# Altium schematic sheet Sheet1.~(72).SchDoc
size A
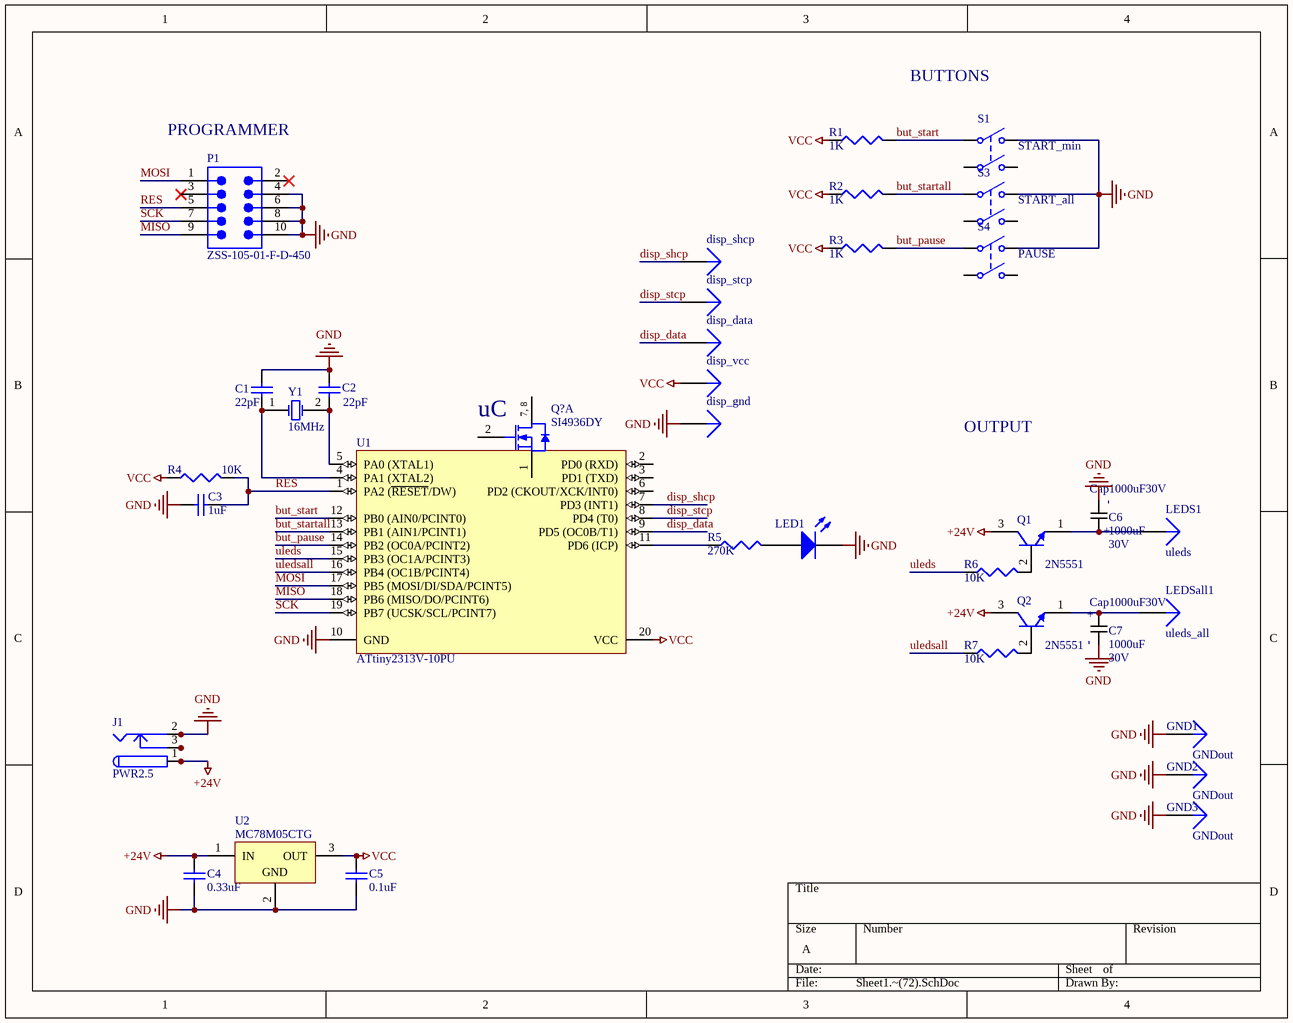
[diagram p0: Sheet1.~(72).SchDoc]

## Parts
C1  value 22pF  [CAPC1608L]  (hidden comment: Cap Semi)
C2  value 22pF  [CAPC1608L]  (hidden comment: Cap Semi)
C3  value 1uF  [CAPC1608L]  (hidden comment: Cap Semi)
C4  value 0.33uF  [CAPC1608L]  (hidden comment: Cap Semi)
C5  value 0.1uF  [CAPC1608L]  (hidden comment: Cap Semi)
C6  Cap1000uF30V  Capasitance: 1000uF  Voltage: 30V  [Cap_1000uF_35V - duplicate]
C7  Cap1000uF30V  Capasitance: 1000uF  Voltage: 30V  [Cap_1000uF_35V - duplicate]
disp_data  uleds_all  [PIN1]  (value not drawn)
disp_gnd  uleds_all  [PIN1]  (value not drawn)
disp_shcp  uleds_all  [PIN1]  (value not drawn)
disp_stcp  uleds_all  [PIN1]  (value not drawn)
disp_vcc  uleds_all  [PIN1]  (value not drawn)
GND1  GNDout  [PIN1]
GND2  GNDout  [PIN1]
GND3  GNDout  [PIN1]
J1  PWR2.5  [PCBComponent_1]
LED1  151051YS04000  [Type 5mm]  (value not drawn)
LEDS1  uleds  [PIN1]
LEDSall1  uleds_all  [PIN1]
P1  ZSS-105-01-F-D-450  [SMTC-ZSS-105-01-X-D-450]
Q1  2N5551  [ONSC-TO-92-3-29-11_AM_BL]
Q2  2N5551  [ONSC-TO-92-3-29-11_AM_BL]
Q?  SI4936DY  [SO-8_N]  (part A of 2)
R1  value 1K  [CAPC1608L]  (hidden comment: Res3)
R2  value 1K  [CAPC1608L]  (hidden comment: Res3)
R3  value 1K  [CAPC1608L]  (hidden comment: Res3)
R4  value 10K  [CAPC1608L]  (hidden comment: Res3)
R5  value 270K  [CAPC1608L]  (hidden comment: Res3)
R6  value 10K  [CAPC1608L]  (hidden comment: Res3)
R7  value 10K  [CAPC1608L]  (hidden comment: Res3)
S1  START_min  [key]
S3  START_all  [key]
S4  PAUSE  [key]
U1  ATtiny2313V-10PU  [20P3]
U2  MC78M05CTG  [TO220]
Y1  16MHz  [PCBComponent_1 - duplicate]

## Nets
+24V: C4.2 J1.1 J1.1A J1.1B Q1.3(C) Q2.3(C) U2.1(IN)
GND: C1.1 C2.1 C3.2 C4.1 C5.1 C6.2(-) C7.2(-) disp_gnd.1 GND1.1 GND2.1 GND3.1 J1.2 J1.2A J1.2B LED1.1(K) P1.4 P1.6 P1.8 P1.10 S1.2(NO1) S3.2(NO1) S4.2(NO1) U1.10(GND) U2.2(GND)
VCC: C5.2 disp_vcc.1 R1.1 R2.1 R3.1 R4.1 U1.20(VCC) U2.3(OUT)
but_pause: R3.2 S4.1(COMMON1) U1.14(PB2_(OC0A/PCINT2))
but_start: R1.2 S1.1(COMMON1) U1.12(PB0_(AIN0/PCINT0))
but_startall: R2.2 S3.1(COMMON1) U1.13(PB1_(AIN1/PCINT1))
disp_data: disp_data.1 U1.9(PD5_(OC0B/T1))
disp_shcp: disp_shcp.1 U1.7(PD3_(INT1))
disp_stcp: disp_stcp.1 U1.8(PD4_(T0))
MISO: P1.9 U1.18(PB6_(MISO/DO/PCINT6))
MOSI: P1.1 U1.17(PB5_(MOSI/DI/SDA/PCINT5))
RES: C3.1 P1.5 R4.2 U1.1(PA2_(~{RESET}/DW))
SCK: P1.7 U1.19(PB7_(UCSK/SCL/PCINT7))
uleds: R6.1 U1.15(PB3_(OC1A/PCINT3))
uledsall: R7.1 U1.16(PB4_(OC1B/PCINT4))
NetC1_2: C1.2 U1.4(PA1_(XTAL2)) Y1.1(OSC1)
NetC2_2: C2.2 U1.5(PA0_(XTAL1)) Y1.2(OSC2)
NetC6_1: C6.1 LEDS1.1 Q1.1(E)
NetC7_1: C7.1 LEDSall1.1 Q2.1(E)
NetJ1_3: J1.3 J1.3A J1.3B
NetLED1_2: LED1.2(A) R5.2
NetQ1_2: Q1.2(B) R6.2
NetQ2_2: Q2.2(B) R7.2
NetQ?_7: Q?.7(D) Q?.8(D)
NetR5_1: R5.1 U1.11(PD6_(ICP))

Not connected (* = marked no-connect by the designer): P1 2* 3*; Q? 1(S) 2(G); S1 3(COMMON2) 4(NO2); S3 3(COMMON2) 4(NO2); S4 3(COMMON2) 4(NO2); U1 2(PD0_(RXD)) 3(PD1_(TXD)) 6(PD2_(CKOUT/XCK/INT0))

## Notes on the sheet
- BUTTONS
- (near P1) PROGRAMMER
- (near Q?) uC
- OUTPUT

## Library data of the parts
C1-C5 = Cap Semi: Capacitor (Semiconductor SIM Model)
disp_data disp_gnd disp_shcp disp_stcp disp_vcc GND1-GND3 LEDS1 LEDSall1 = Plug
J1 = PWR2.5: Low Voltage Power Supply Connector
LED1 = CMP-1488-00010-1: THT LED round mono-color color lens, WL-TMRW, Yellow; Manufacturer: Wuerth Elektronik
P1 = CMP-1024-00461-1: Manufacturer: Samtec; Pitch: 2.54 mm
Q1 Q2 = CMP-1048-01479-1: Amplifier Transistor, NPN Silicon, 3-Pin TO-92, Pb-Free, Tape and Reel; PartNumber: 2N5551RL1G; Manufacturer: On Semiconductor; fT Min (MHz): 100; IC Continuous (A): 0.6
Q? = SI4936DY: Dual N-Channel 30V (D-S)  MOSFET
R1-R7 = Res3: Resistor
S1 S3 S4 = SW-DPST: Double-Pole, Single-Throw Switch
U1 = CMP-0093-00017-1: Low Power tinyAVR® 8-Bit Microcontroller, 2K Flash Memory, 10MHz, Industrial Temperature, 20-Lead PDIP, Pb-Free
U2 = CMP-0244-00483-1: Positive Voltage Regulator, 5V, 3-Pin TO-220
Y1 = XTAL: Crystal Oscillator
